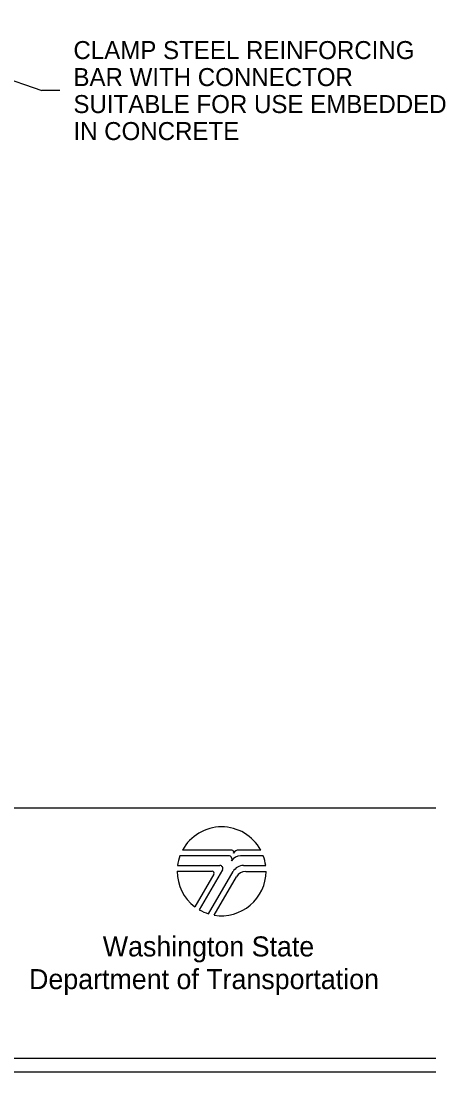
# Model space of a CAD drawing. Extents: x 99888 to 103177, y 100000 to 102076.
# Drawn here: x 102071 to 102434, y 100000 to 100934 of the extents above; entities that cross this region are included whole.
import ezdxf

# ---------------------------------------------------------------- set-up
doc = ezdxf.new("R2010")
doc.units = 0
for name, color, linetype in [('Level 15', 7, 'Continuous'), ('Level 20', 7, 'Continuous'), ('SH_GI_PlotLimits', 7, 'Continuous'), ('SH_GI_SheetBorder', 7, 'Continuous'), ('SH_GI_SheetTextInCells', 7, 'Continuous'), ('SH_GI_WSDOTLogo', 7, 'Continuous')]:
    doc.layers.add(name, color=color, linetype=linetype)

msp = doc.modelspace()

# ---------------------------------------------------------------- linework, layer by layer
at = {"layer": 'Level 15'}
for p in [(101785.03, 100978.35), (102105.87, 100872.42), (102105.87, 100872.42)]:
    msp.add_line(p, (102089.87, 100872.42), dxfattribs=at)
at = {"layer": 'SH_GI_PlotLimits'}
msp.add_lwpolyline([(99888.5, 100000), (103150, 100000), (103150, 102075.5), (99888.5, 102075.5)], close=True, dxfattribs=at)
msp.add_lwpolyline([(99888.5, 100000), (103150, 100000), (103150, 102075.5), (99888.5, 102075.5)], close=True, dxfattribs=at)
at = {"layer": 'SH_GI_SheetBorder'}
for p, q in [((100024.39, 100234.91), (103137.64, 100234.91)), ((100024.39, 100234.91), (103137.64, 100234.91)), ((100024.39, 100012.35), (103137.64, 100012.35)), ((100024.39, 100012.35), (103137.64, 100012.35))]:
    msp.add_line(p, q, dxfattribs=at)
at = {"layer": 'SH_GI_WSDOTLogo'}
for p, q in [((102255.93, 100192.11), (102212.5, 100192.11)), ((102255.93, 100192.11), (102212.5, 100192.11)), ((102258.61, 100197.24), (102214.83, 100197.24)), ((102258.61, 100197.24), (102214.83, 100197.24)), ((102284.31, 100197.24), (102264.97, 100197.24)), ((102284.31, 100197.24), (102264.97, 100197.24)), ((102266.52, 100192.11), (102266.51, 100192.11)), ((102266.52, 100192.11), (102266.51, 100192.11)), ((102286.64, 100192.11), (102266.52, 100192.11)), ((102286.64, 100192.11), (102266.52, 100192.11)), ((102210.39, 100183.54), (102248.07, 100183.54)), ((102210.39, 100183.54), (102248.07, 100183.54)), ((102250.32, 100179.65), (102229.7, 100144.24)), ((102250.32, 100179.65), (102229.7, 100144.24)), ((102269.05, 100183.54), (102288.77, 100183.54)), ((102269.05, 100183.54), (102288.77, 100183.54)), ((102210.04, 100178.39), (102241.19, 100178.39)), ((102210.04, 100178.39), (102241.19, 100178.39)), ((102242.6, 100175.96), (102225.7, 100146.9)), ((102242.6, 100175.96), (102225.7, 100146.9)), ((102238.05, 100140.59), (102259.78, 100178.19)), ((102238.05, 100140.59), (102259.78, 100178.19)), ((102243.09, 100139.41), (102262.81, 100173.57)), ((102243.09, 100139.41), (102262.81, 100173.57)), ((102270.97, 100178.27), (102289.09, 100178.27)), ((102270.97, 100178.27), (102289.09, 100178.27))]:
    msp.add_line(p, q, dxfattribs=at)
for centre, radius, start, end in [((102249.58, 100178.4), 39.52, 28.47865, 151.53204), ((102249.58, 100178.4), 39.52, 28.47865, 151.53204), ((102249.58, 100178.4), 39.52, 159.69598, 172.50569), ((102249.58, 100178.4), 39.52, 159.69598, 172.50569), ((102255.93, 100189.19), 2.92, 327.8418, 89.99855), ((102255.93, 100189.19), 2.92, 327.8418, 89.99855), ((102266.5, 100182.54), 9.57, 89.99529, 147.82376), ((102266.5, 100182.54), 9.57, 89.99529, 147.82376), ((102258.61, 100195.46), 1.78, 329.87418, 90.00328), ((102258.61, 100195.46), 1.78, 329.87418, 90.00328), ((102264.98, 100191.57), 5.68, 90.00721, 148.16763), ((102264.98, 100191.57), 5.68, 90.00721, 148.16763), ((102249.58, 100178.4), 39.52, 7.49431, 20.29406), ((102249.58, 100178.4), 39.52, 7.49431, 20.29406), ((102248.08, 100180.96), 2.59, 329.76834, 90), ((102248.08, 100180.96), 2.59, 329.76834, 90), ((102269.05, 100172.85), 10.7, 90, 149.99738), ((102269.05, 100172.85), 10.7, 90, 149.99738), ((102249.58, 100178.4), 39.52, 179.99864, 232.84327), ((102249.58, 100178.4), 39.52, 179.99864, 232.84327), ((102241.2, 100176.77), 1.62, 329.74356, 90), ((102241.2, 100176.77), 1.62, 329.74356, 90), ((102249.58, 100178.4), 39.52, 260.54554, 359.80857), ((102249.58, 100178.4), 39.52, 260.54554, 359.80857), ((102270.96, 100168.87), 9.41, 90, 150.05432), ((102270.96, 100168.87), 9.41, 90, 150.05432), ((102249.58, 100178.4), 39.52, 239.79292, 253.0448), ((102249.58, 100178.4), 39.52, 239.79292, 253.0448)]:
    msp.add_arc(centre, radius, start, end, dxfattribs=at)

# ---------------------------------------------------------------- texts
at = {"layer": 'Level 20'}
for s, p in [('CLAMP STEEL REINFORCING ', (102117.87, 100900.42)), ('BAR WITH CONNECTOR ', (102117.87, 100876.42)), ('SUITABLE FOR USE EMBEDDED', (102117.87, 100852.42)), ('IN CONCRETE', (102117.87, 100828.42))]:
    msp.add_text(s, height=16, dxfattribs=at).set_placement(p)
at = {"layer": 'SH_GI_SheetTextInCells'}
for s, p in [('Washington State', (102143.96, 100102.71)), ('Washington State', (102143.96, 100102.71)), ('Department of Transportation', (102078.46, 100073.66)), ('Department of Transportation', (102078.46, 100073.66))]:
    msp.add_text(s, height=17.8042, dxfattribs=at).set_placement(p)

doc.saveas('drawing.dxf')
